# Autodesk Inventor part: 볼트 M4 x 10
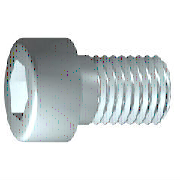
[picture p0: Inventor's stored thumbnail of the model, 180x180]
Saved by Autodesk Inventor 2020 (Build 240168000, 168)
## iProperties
Created: 2012-02
Part Number: 볼트 M4 x 10
Material: 스테인리스강
Description: 6각 소켓 머리 캡 나사
Document SubType Name: Modeling
Standard: ISO 4762
Designer: mduedu
Standard Revision: Fourth edition 2004-03-01
Standards Organization: ISO
Language: ko-KR
Size Designation: M4 x 10
Categories: <MemberInstance><Categories><Category DisplayName="조임쇠" InternalName="e4da775c-781d-43d5-af7c-5136215cf5a6" Mnemonic="FSTN"><Category DisplayName="볼트" InternalN
Density: 8.08 g/cm^3
Appearance: 반광택
IsCustomPart: 0
Author: mduedu
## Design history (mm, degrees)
sketch "스케치1"
  geometry: L1 (-1, 0)-(10, 0); L2 (10, 0)-(10, 2); L3 (10, 2)-(1.75, 2); L4 (1.75, 2)-(1.32, 2); L5 (1.32, 2)-(0, 2); L6 (0, 2)-(0, 3.5); L7 (0, 3.5)-(-4, 3.5); L8 (-4, 3.5)-(-4, 1.732); L9 (-4, 1.732)-(-2, 1.732); L10 (-2, 1.732)-(-1, 0); L11 (-6.8, 0)-(12.8, 0) reference; L12 (0, -0.7)-(0, 4.2) reference; L13 (1.75, 2)-(0, 2)
  constraints: 22 end point, 6 parallel, 2 collinear, 2 perpendicular, 1 horizontal, 1 point on line
  dimensions: "d1" = 8.25 distance from line of L3.end L2 (= GEL); "d2" = 0.42952 distance of L4.end L3.end (computed from GAL); "d3" = 4 distance between parallel lines of L8 L6 (= KOH); "d4" = 2 distance of L8.end L9.end (= INTI); "d5" = 60 deg angle of L10 L1; "d6" = 4 diameter of L3 L1 (= GD); "d7" = 4 diameter of L5 L1 (= BDM); "d8" = 3.4641 diameter of L9 L1 (= 1.1547 x SW); "d9" = 7 diameter of L7 L1 (= KOD); "d26" = 10 distance between parallel lines of L12 L2 (= NLG)
revolve "본체" sketch "스케치1" stored, may be unused: angle "d10" = 90 deg
sketch "스케치2"
  geometry: L1 (0, -4.9)-(0, 4.9) reference; L2 (-4.9, 0)-(4.9, 0) reference; L3 (1.732, 0)-(0.866, -1.5); L4 (0.866, -1.5)-(-0.866, -1.5); L5 (-0.866, -1.5)-(-1.732, 0); L6 (-1.732, 0)-(-0.866, 1.5); L7 (-0.866, 1.5)-(0.866, 1.5); L8 (0.866, 1.5)-(1.732, 0); 2 further points
  constraints: 12 end point, 1 coincident, 1 horizontal alignment, 1 point on line, 12 other
extrude "슬롯" join sketch "스케치2" stored distance "d11" = 10; taper "d12" = 0 deg
workplane "Work Plane1"
fillet "Fillet2" dims "d30" = 0.1 (= R)
body "Solid1"
fillet "모깎기1" dims "d17" = 0.4 (= RR)
feature "스레드" dims "d13" = 8.25 (= GEL), "d14" = 0
chamfer "모따기1" distance "d15" = 0.42941 (= -0.5 x SPD + 0.5 x GD); stored, may be unused: second distance "d16" = 0.42941 (= GUL), angle "d27" = 45 deg
other parameters: "GD" = 4 [user parameter; used in 2 equation terms], "NLG" = 10 [user parameter; used in 1 equation term], "GEL" = 8.25 [user parameter; used in 2 equation terms], "KOD" = 7 [user parameter; used in 1 equation term], "KOH" = 4 [user parameter; used in 1 equation term], "INTI" = 2 [user parameter; used in 1 equation term], "GAL" = 0.42941 (= 0.61345 x PTC) [user parameter; used in 1 equation term], "GUL" = 0.42941 (= 0.61345 x PTC) [user parameter; used in 1 equation term], "BDM" = 4 (= NND) [user parameter; used in 1 equation term], "SW" = 3 [user parameter; used in 2 equation terms], "RR" = 0.4 [user parameter; used in 1 equation term], "SPD" = 3.14117 (= NND - 1.2269 x PTC) [user parameter; used in 1 equation term], "d19" = 0, "d28" = 0, "d29" = 0, "R" = 0.1 [user parameter; used in 1 equation term], "TOA" = 30 deg [user parameter], "GD1" = 3.14117 (= THREADDIA - 1.2269 x PTC) [user parameter], "THREADDIA" = 4 [user parameter; used in 1 equation term], "FAWI" = 45 deg [user parameter], "TPU" = 14.28571 (computed from PTC) [user parameter], "PTC" = 0.7 [user parameter; used in 5 equation terms], "NND" = 4 [user parameter; used in 2 equation terms], "E0" = 3.465 (= 1.155 x SW) [user parameter]
